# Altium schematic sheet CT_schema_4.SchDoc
size 357 x 214 mm
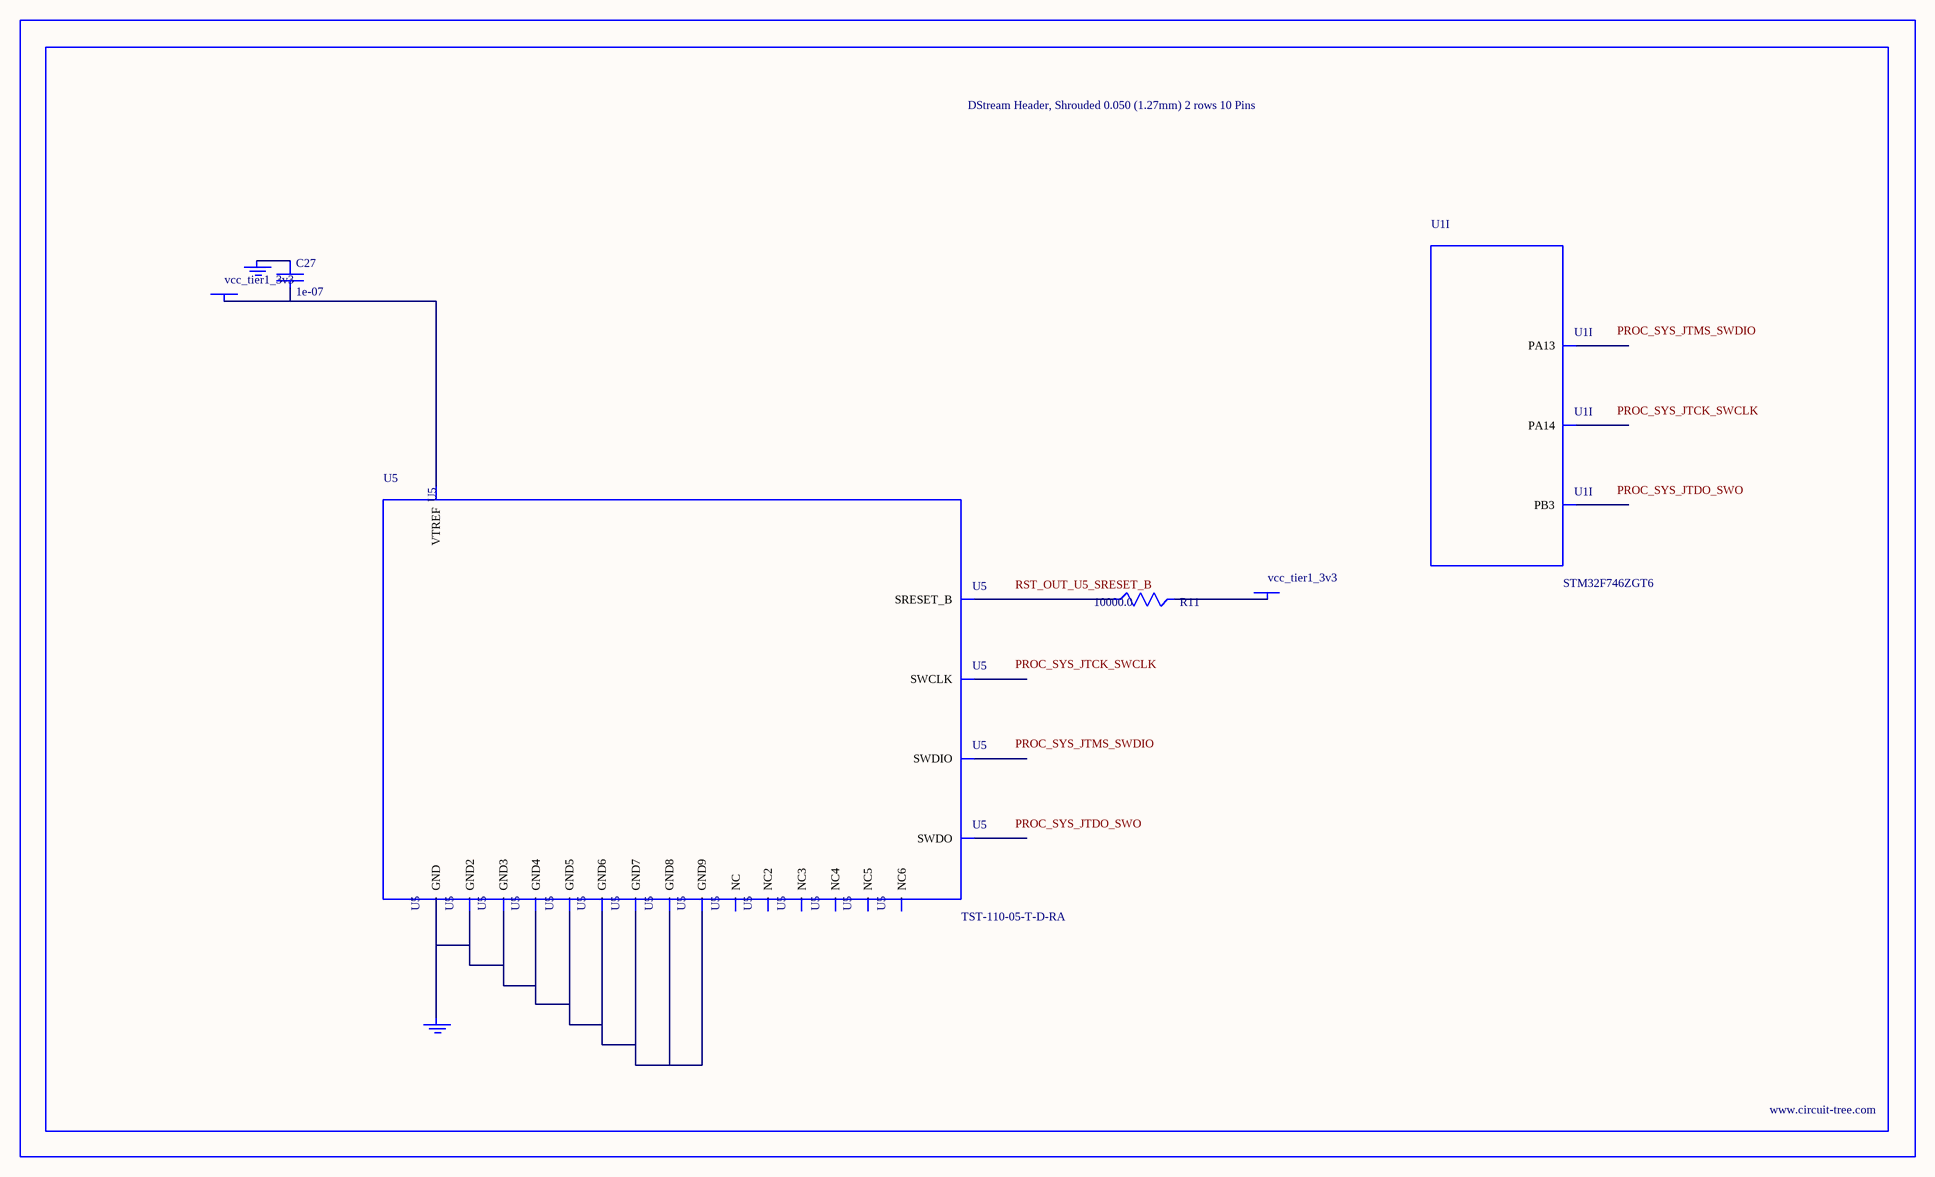
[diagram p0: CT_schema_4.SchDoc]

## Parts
BORDER3  (no value)
C27  1e-07  [C0402]
GND_INSTANCE_3_0  (no value)
GND_INSTANCE_3_1  (no value)
POWER_INSTANCE_3_0  vcc_tier1_3v3
POWER_INSTANCE_3_1  vcc_tier1_3v3
R11  10000.0  [R0603]
U1  STM32F746ZGT6  [LQFP144]  (part I of 12)
U5  TST-110-05-T-D-RA  [TST-110-05-T-D-RA]

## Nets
NetC27_1: C27.1 GND_INSTANCE_3_0.0(GND)
NetC27_2: C27.2 POWER_INSTANCE_3_0.0(PWR) U5.1(VTREF)
NetGND_INSTANCE_3_1_0: GND_INSTANCE_3_1.0(GND) U5.4(GND) U5.6(GND2) U5.8(GND3) U5.10(GND4) U5.12(GND5) U5.14(GND6) U5.16(GND7) U5.18(GND8) U5.20(GND9)
NetPOWER_INSTANCE_3_1_0: POWER_INSTANCE_3_1.0(PWR) R11.2
NetR11_1: R11.1 U5.15(SRESET_B)

Not connected (* = marked no-connect by the designer): U1 105(PA13) 109(PA14) 133(PB3); U5 2(NC) 3(NC2) 5(NC3) 7(SWDIO) 9(SWCLK) 11(NC4) 13(SWDO) 17(NC5) 19(NC6)

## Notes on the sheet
- Labels drawn without touching a wire or pin: PROC_SYS_JTCK_SWCLK, PROC_SYS_JTDO_SWO, PROC_SYS_JTMS_SWDIO, RST_OUT_U5_SRESET_B

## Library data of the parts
BORDER3 = BORDER_PAGE3
C27 = C0402C104K3RACTU
GND_INSTANCE_3_0 GND_INSTANCE_3_1 = GND
POWER_INSTANCE_3_0 POWER_INSTANCE_3_1 = PWR
R11 = RC0603JR-0710KL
